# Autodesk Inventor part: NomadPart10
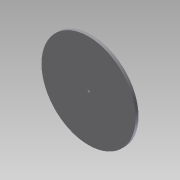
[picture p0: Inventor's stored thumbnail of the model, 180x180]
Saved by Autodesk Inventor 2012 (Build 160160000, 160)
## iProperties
Created: 2012-10
Part Number: NomadPart10
Material: Default
Document SubType Name: Modeling
Designer: TechShop Member
Density: 1 g/cm^3
Author: TechShop Member
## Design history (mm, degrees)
sketch "Sketch1"
  geometry: C1 r 104.775 at (0, 0); 1 further point
  constraints: 1 centre point, 1 coincident
  dimensions: "d0" = 209.55 diameter of C1
extrude "Extrusion1" new body sketch "Sketch1" distance "d1" = 6.35; taper "d2" = 0 deg
sketch "Sketch2"
  geometry: C1 r 104.775 at (0, 0) reference; 1 further point
  constraints: 1 coincident
hole "Hole1" sketch "Sketch2" at (0, 0) diameter "d3" = 5.207; stored, may be unused: countersink angle "d7" = 82 deg, drill point angle "d9" = 118 deg; dims "d4" = 19.05, "d5" = 9.525, "d6" = 6.35, "d8" = 25.4
body "Solid1"
